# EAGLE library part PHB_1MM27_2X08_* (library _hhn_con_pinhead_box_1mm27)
Pin Header Box-Type, 1.27mm/0.5"/50mil Pitch, 2x08 Circuits Note: see library description for an important note about THT-version
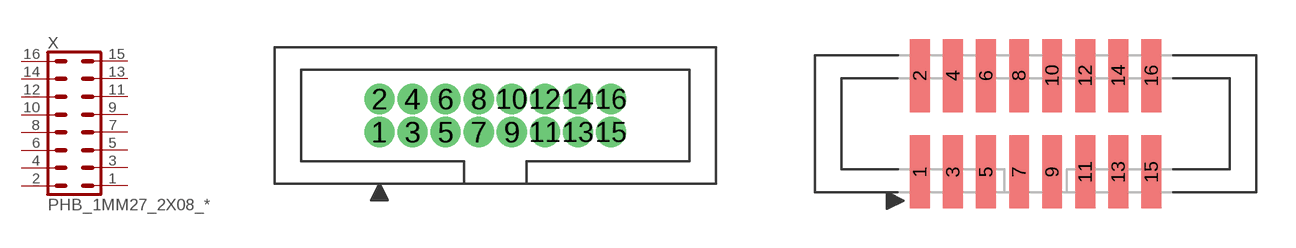
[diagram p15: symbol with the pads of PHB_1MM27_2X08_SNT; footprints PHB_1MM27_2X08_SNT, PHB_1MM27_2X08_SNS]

Designator prefix X

## PHB_1MM27_2X08_SNT  [PHB_1MM27_2X08_SNT]
1  1  pas
2  2  pas
3  3  pas
4  4  pas
5  5  pas
6  6  pas
7  7  pas
8  8  pas
9  9  pas
10  10  pas
11  11  pas
12  12  pas
13  13  pas
14  14  pas
15  15  pas
16  16  pas

## PHB_1MM27_2X08_SNS  [PHB_1MM27_2X08_SNS]
Pads as for PHB_1MM27_2X08_SNT

## Footprint PHB_1MM27_2X08_SNT (pad centres in mm)
Pin Header Box-Type, 1.27mm Pitch, 2x08 circuits, Straight, No Locking, THT Important Note: Diameter in this lbr is set to a specific value (NOT 'auto' = 0), this is ignored by actual eagle versions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
drill 0.65 pad 1 round: 1 -4.445,-0.635; 2 -4.445,0.635; 3 -3.175,-0.635; 4 -3.175,0.635; 5 -1.905,-0.635; 6 -1.905,0.635; 7 -0.635,-0.635; 8 -0.635,0.635; 9 0.635,-0.635; 10 0.635,0.635; 11 1.905,-0.635; 12 1.905,0.635; 13 3.175,-0.635; 14 3.175,0.635; 15 4.445,-0.635; 16 4.445,0.635

## Footprint PHB_1MM27_2X08_SNS (pad centres in mm)
Pin Header Box-Type, 1.27mm Pitch, 2x08 circuits, Straight, No Locking, SMT
smd 0.76 x 2.8: 1 -4.445,-1.85; 2 -4.445,1.85; 3 -3.175,-1.85; 4 -3.175,1.85; 5 -1.905,-1.85; 6 -1.905,1.85; 7 -0.635,-1.85; 8 -0.635,1.85; 9 0.635,-1.85; 10 0.635,1.85; 11 1.905,-1.85; 12 1.905,1.85; 13 3.175,-1.85; 14 3.175,1.85; 15 4.445,-1.85; 16 4.445,1.85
